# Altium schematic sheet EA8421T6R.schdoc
size 127 x 101 mm
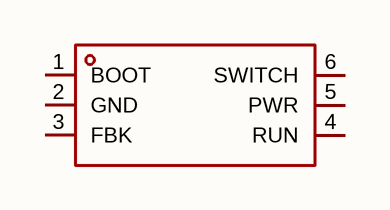
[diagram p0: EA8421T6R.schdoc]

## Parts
U?  ea8421t6r  [SOT-23-6_L2.9-W1.6-P0.95-LS2.8-BR]  (value not drawn)

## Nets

Not connected (* = marked no-connect by the designer): U? 1(BOOT) 2(GND) 3(FBK) 4(RUN) 5(PWR) 6(SWITCH)

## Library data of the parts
U? = ea8421t6r: 功能类型:降压型;工作电压:5V~40V;输出电压:800mV~40V;输出电流:800mA;输出类型:可调;; Manufacturer: everanalog(申风); AddInBom: yes; ModelId: 18da8f6c14a34920b3e136b5c401a119; ModelName: SOT-23-6_L2.9-W1.6-H1.5-LS2.8-P0.95; ModelTransform: 110.73671,114.173,0,180,0,0,0.001,-0.003,0; Function: 降压型; Voltage - Supply: 5V~40V; Output Current: 800mA; Frequency - Switching: 600kHz; Synchronous Rectifier: 否; Number of Outputs: 1; Topology: 降压式; Quiescent Current: 400uA; Switch tube (built-in/external): 内置; Output Type: 可调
